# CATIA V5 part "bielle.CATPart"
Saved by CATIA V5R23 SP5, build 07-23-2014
Part number: bielle
Definition: bielle
Source: made
Bounding box of the stored display mesh (mm): x -12.5 to 77.5, y -12.5 to 12.5, z 0 to 6
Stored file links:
  C:\wamp\www\COURS\CONCEPTION GMP1\TITRE 01-CATIA VOLUMIQUE\05--ACTIONNEUR DE VANNE\prof\CORRECTION\Assemblage\bielle.CATPart
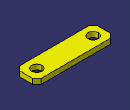
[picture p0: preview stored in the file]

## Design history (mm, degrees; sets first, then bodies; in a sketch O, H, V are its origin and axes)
Set1
  Plane1 "Plan.1": type Offset, RefPlane face of Solid1, Offset 23, reversed
Body1 "NONE" (main body)
  Solid1 "Manifold Solid #148": solid without history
